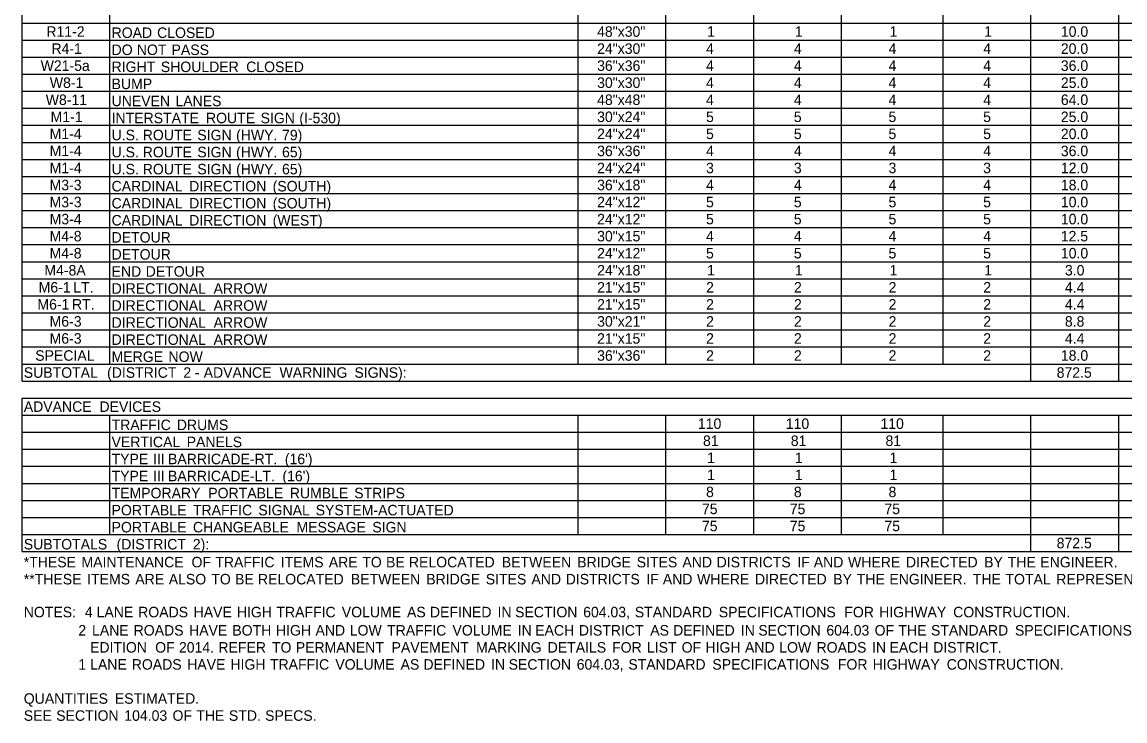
# Model space of a CAD drawing. Extents: x 542596 to 1930787, y -1948294 to 596640.
# Drawn here: x 546363 to 546993, y -1945748 to -1945349 of the extents above; entities that cross this region are included whole.
import ezdxf

# ---------------------------------------------------------------- set-up
doc = ezdxf.new("R2010")
doc.units = 0
doc.layers.add('Default', color=7, linetype='Continuous')

msp = doc.modelspace()

# ---------------------------------------------------------------- linework, layer by layer
at = {"layer": 'Default'}
for p, q in [((546362.8, -1945554.02), (546362.8, -1945125.02)), ((546362.8, -1945554.02), (546362.8, -1945125.02)), ((546413.02, -1945544.27), (546413.02, -1945193.27)), ((546413.02, -1945544.27), (546413.02, -1945193.27)), ((546680.65, -1945544.27), (546680.65, -1945193.27)), ((546680.65, -1945544.27), (546680.65, -1945193.27)), ((546730.87, -1945544.27), (546730.87, -1945193.27)), ((546730.87, -1945544.27), (546730.87, -1945193.27)), ((546781.08, -1945544.27), (546781.08, -1945193.27)), ((546831.29, -1945544.27), (546831.29, -1945193.27)), ((546831.29, -1945544.27), (546831.29, -1945193.27)), ((546889.3, -1945544.27), (546889.3, -1945193.27)), ((546939.52, -1945544.27), (546939.52, -1945193.27)), ((546939.52, -1945554.02), (546939.52, -1945193.27)), ((546989.73, -1945554.02), (546989.73, -1945193.27)), ((546989.73, -1945554.02), (546989.73, -1945193.27)), ((546362.8, -1945349.27), (547426.53, -1945349.27)), ((546781.08, -1945534.52), (546781.08, -1945349.27)), ((546362.8, -1945359.02), (547426.53, -1945359.02)), ((546362.8, -1945368.77), (547426.53, -1945368.77)), ((546362.8, -1945378.52), (547426.53, -1945378.52)), ((546362.8, -1945388.27), (547426.53, -1945388.27)), ((546362.8, -1945398.02), (547426.53, -1945398.02)), ((546362.8, -1945407.77), (547426.53, -1945407.77)), ((546362.8, -1945417.52), (547426.53, -1945417.52)), ((546362.8, -1945427.27), (547426.53, -1945427.27)), ((546362.8, -1945437.02), (547426.53, -1945437.02)), ((546362.8, -1945446.77), (547426.53, -1945446.77)), ((546362.8, -1945456.52), (547426.53, -1945456.52)), ((546362.8, -1945466.27), (547426.53, -1945466.27)), ((546362.8, -1945476.02), (547426.53, -1945476.02)), ((546362.8, -1945485.77), (547426.53, -1945485.77)), ((546362.8, -1945495.52), (547426.53, -1945495.52)), ((546362.8, -1945505.27), (547426.53, -1945505.27)), ((546362.8, -1945515.02), (547426.53, -1945515.02)), ((546362.8, -1945524.77), (547426.53, -1945524.77)), ((546362.8, -1945534.52), (547426.53, -1945534.52)), ((546362.8, -1945544.27), (546730.87, -1945544.27)), ((546362.8, -1945544.27), (547426.53, -1945544.27)), ((546730.87, -1945544.27), (546781.08, -1945544.27)), ((546781.08, -1945544.27), (546831.29, -1945544.27)), ((546362.8, -1945554.02), (547426.53, -1945554.02)), ((546362.8, -1945563.77), (547426.53, -1945563.77)), ((546362.8, -1945651.52), (546362.8, -1945563.77)), ((546362.8, -1945651.52), (546362.8, -1945563.77)), ((546413.02, -1945563.77), (547267.12, -1945563.77)), ((546362.8, -1945573.52), (547426.53, -1945573.52)), ((546413.02, -1945641.77), (546413.02, -1945573.52)), ((546413.02, -1945641.77), (546413.02, -1945573.52)), ((546680.65, -1945641.77), (546680.65, -1945573.52)), ((546680.65, -1945641.77), (546680.65, -1945573.52)), ((546730.87, -1945641.77), (546730.87, -1945573.52)), ((546730.87, -1945641.77), (546730.87, -1945573.52)), ((546781.08, -1945641.77), (546781.08, -1945573.52)), ((546781.08, -1945641.77), (546781.08, -1945573.52)), ((546831.29, -1945641.77), (546831.29, -1945573.52)), ((546831.29, -1945641.77), (546831.29, -1945573.52)), ((546889.3, -1945641.77), (546889.3, -1945573.52)), ((546939.52, -1945641.77), (546939.52, -1945573.52)), ((546939.52, -1945651.52), (546939.52, -1945573.52)), ((546989.73, -1945651.52), (546989.73, -1945573.52)), ((546989.73, -1945651.52), (546989.73, -1945573.52)), ((546362.8, -1945583.27), (547426.53, -1945583.27)), ((546362.8, -1945593.02), (547426.53, -1945593.02)), ((546362.8, -1945602.77), (547426.53, -1945602.77)), ((546362.8, -1945612.52), (547426.53, -1945612.52)), ((546362.8, -1945622.27), (547426.53, -1945622.27)), ((546362.8, -1945632.02), (547426.53, -1945632.02)), ((546680.65, -1945632.02), (547426.53, -1945632.02)), ((546362.8, -1945641.77), (546680.65, -1945641.77)), ((546362.8, -1945641.77), (547426.53, -1945641.77)), ((546362.8, -1945651.52), (547426.53, -1945651.52))]:
    msp.add_line(p, q, dxfattribs=at)

# ---------------------------------------------------------------- texts
for s, p in [('R11-2', (546376.72, -1945357.15)), ('ROAD', (546413.99, -1945357.82)), (' CLOSED', (546437.77, -1945357.82)), ('48"x30"', (546691.56, -1945357.15)), ('1', (546754.41, -1945357.15)), ('1', (546804.62, -1945357.15)), ('1', (546858.74, -1945357.15)), ('1', (546912.85, -1945357.15)), ('10.0', (546956.67, -1945357.15)), ('R4-1', (546379.6, -1945366.9)), ('DO', (546413.99, -1945367.57)), (' NOT', (546426.19, -1945367.57)), (' PASS', (546446.05, -1945367.57)), ('24"x30"', (546691.56, -1945366.9)), ('4', (546753.85, -1945366.9)), ('4', (546804.06, -1945366.9)), ('4', (546858.17, -1945366.9)), ('4', (546912.28, -1945366.9)), ('20.0', (546956.67, -1945366.9)), ('W21-5a', (546373.42, -1945376.65)), ('RIGHT', (546413.99, -1945377.32)), (' SHOULDER', (546439.9, -1945377.32)), (' CLOSED', (546488.7, -1945377.32)), ('36"x36"', (546691.56, -1945376.65)), ('4', (546753.85, -1945376.65)), ('4', (546804.06, -1945376.65)), ('4', (546858.17, -1945376.65)), ('4', (546912.28, -1945376.65)), ('36.0', (546956.67, -1945376.65)), ('W8-1', (546378.67, -1945386.4)), ('BUMP', (546413.99, -1945387.07)), ('30"x30"', (546691.56, -1945386.4)), ('4', (546753.85, -1945386.4)), ('4', (546804.06, -1945386.4)), ('4', (546858.17, -1945386.4)), ('4', (546912.28, -1945386.4)), ('25.0', (546956.67, -1945386.4)), ('W8-11', (546376.34, -1945396.15)), ('UNEVEN', (546413.99, -1945396.82)), (' LANES', (546448.25, -1945396.82)), ('48"x48"', (546691.56, -1945396.15)), ('4', (546753.85, -1945396.15)), ('4', (546804.06, -1945396.15)), ('4', (546858.17, -1945396.15)), ('4', (546912.28, -1945396.15)), ('64.0', (546956.67, -1945396.15)), ('M1-1', (546379.13, -1945405.9)), ('INTERSTATE', (546413.99, -1945406.57)), (' ROUTE', (546465.72, -1945406.57)), (' SIGN', (546496.94, -1945406.57)), (' (I-530)', (546519.08, -1945406.57)), ('30"x24"', (546691.56, -1945405.9)), ('5', (546753.81, -1945405.9)), ('5', (546804.02, -1945405.9)), ('5', (546858.13, -1945405.9)), ('5', (546912.25, -1945405.9)), ('25.0', (546956.67, -1945405.9)), ('M1-4', (546378.57, -1945415.65)), ('U.S.', (546413.99, -1945416.32)), (' ROUTE', (546429.56, -1945416.32)), (' SIGN', (546460.79, -1945416.32)), (' (HWY.', (546482.93, -1945416.32)), (' 79)', (546509.2, -1945416.32)), ('24"x24"', (546691.56, -1945415.65)), ('5', (546753.81, -1945415.65)), ('5', (546804.02, -1945415.65)), ('5', (546858.13, -1945415.65)), ('5', (546912.25, -1945415.65)), ('20.0', (546956.67, -1945415.65)), ('M1-4', (546378.57, -1945425.4)), ('U.S.', (546413.99, -1945426.07)), (' ROUTE', (546429.56, -1945426.07)), (' SIGN', (546460.79, -1945426.07)), (' (HWY.', (546482.93, -1945426.07)), (' 65)', (546509.2, -1945426.07)), ('36"x36"', (546691.56, -1945425.4)), ('4', (546753.85, -1945425.4)), ('4', (546804.06, -1945425.4)), ('4', (546858.17, -1945425.4)), ('4', (546912.28, -1945425.4)), ('36.0', (546956.67, -1945425.4)), ('M1-4', (546378.57, -1945435.15)), ('U.S.', (546413.99, -1945435.82)), (' ROUTE', (546429.56, -1945435.82)), (' SIGN', (546460.79, -1945435.82)), (' (HWY.', (546482.93, -1945435.82)), (' 65)', (546509.2, -1945435.82)), ('24"x24"', (546691.56, -1945435.15)), ('3', (546753.83, -1945435.15)), ('3', (546804.04, -1945435.15)), ('3', (546858.16, -1945435.15)), ('3', (546912.27, -1945435.15)), ('12.0', (546956.67, -1945435.15)), ('M3-3', (546378.55, -1945444.9)), ('36"x18"', (546691.56, -1945444.9)), ('4', (546753.85, -1945444.9)), ('4', (546804.06, -1945444.9)), ('4', (546858.17, -1945444.9)), ('4', (546912.28, -1945444.9)), ('18.0', (546956.67, -1945444.9)), ('CARDINAL', (546413.99, -1945445.57)), (' DIRECTION', (546456.09, -1945445.57)), (' (SOUTH)', (546503.84, -1945445.57)), ('M3-3', (546378.55, -1945454.65)), ('CARDINAL', (546413.99, -1945455.32)), (' DIRECTION', (546456.09, -1945455.32)), (' (SOUTH)', (546503.84, -1945455.32)), ('24"x12"', (546691.56, -1945454.65)), ('5', (546753.81, -1945454.65)), ('5', (546804.02, -1945454.65)), ('5', (546858.13, -1945454.65)), ('5', (546912.25, -1945454.65)), ('10.0', (546956.67, -1945454.65)), ('M3-4', (546378.57, -1945464.4)), ('CARDINAL', (546413.99, -1945465.07)), (' DIRECTION', (546456.09, -1945465.07)), (' (WEST)', (546503.84, -1945465.07)), ('24"x12"', (546691.56, -1945464.4)), ('5', (546753.81, -1945464.4)), ('5', (546804.02, -1945464.4)), ('5', (546858.13, -1945464.4)), ('5', (546912.25, -1945464.4)), ('10.0', (546956.67, -1945464.4)), ('M4-8', (546378.55, -1945474.15)), ('DETOUR', (546413.99, -1945474.82)), ('30"x15"', (546691.56, -1945474.15)), ('4', (546753.85, -1945474.15)), ('4', (546804.06, -1945474.15)), ('4', (546858.17, -1945474.15)), ('4', (546912.28, -1945474.15)), ('12.5', (546956.63, -1945474.15)), ('M4-8', (546378.55, -1945483.9)), ('DETOUR', (546413.99, -1945484.57)), ('24"x12"', (546691.56, -1945483.9)), ('5', (546753.81, -1945483.9)), ('5', (546804.02, -1945483.9)), ('5', (546858.13, -1945483.9)), ('5', (546912.25, -1945483.9)), ('10.0', (546956.67, -1945483.9)), ('M4-8A', (546375.56, -1945493.65)), ('END', (546413.99, -1945494.32)), (' DETOUR', (546431.25, -1945494.32)), ('24"x18"', (546691.56, -1945493.65)), ('1', (546754.41, -1945493.65)), ('1', (546804.62, -1945493.65)), ('1', (546858.74, -1945493.65)), ('1', (546912.85, -1945493.65)), ('3.0', (546959, -1945493.65)), ('M6-1', (546372.28, -1945503.4)), (' LT.', (546389.83, -1945503.4)), ('DIRECTIONAL', (546413.99, -1945504.07)), (' ARROW', (546470.06, -1945504.07)), ('21"x15"', (546691.56, -1945503.4)), ('2', (546753.86, -1945503.4)), ('2', (546804.08, -1945503.4)), ('2', (546858.19, -1945503.4)), ('2', (546912.3, -1945503.4)), ('4.4', (546959, -1945503.4)), ('M6-1', (546371.58, -1945513.15)), (' RT.', (546389.13, -1945513.15)), ('DIRECTIONAL', (546413.99, -1945513.82)), (' ARROW', (546470.06, -1945513.82)), ('21"x15"', (546691.56, -1945513.15)), ('2', (546753.86, -1945513.15)), ('2', (546804.08, -1945513.15)), ('2', (546858.19, -1945513.15)), ('2', (546912.3, -1945513.15)), ('4.4', (546959, -1945513.15)), ('M6-3', (546378.55, -1945522.9)), ('DIRECTIONAL', (546413.99, -1945523.57)), (' ARROW', (546470.06, -1945523.57)), ('30"x21"', (546691.56, -1945522.9)), ('2', (546753.86, -1945522.9)), ('2', (546804.08, -1945522.9)), ('2', (546858.19, -1945522.9)), ('2', (546912.3, -1945522.9)), ('8.8', (546958.98, -1945522.9)), ('M6-3', (546378.55, -1945532.65)), ('DIRECTIONAL', (546413.99, -1945533.32)), (' ARROW', (546470.06, -1945533.32)), ('21"x15"', (546691.56, -1945532.65)), ('2', (546753.86, -1945532.65)), ('2', (546804.08, -1945532.65)), ('2', (546858.19, -1945532.65)), ('2', (546912.3, -1945532.65)), ('4.4', (546959, -1945532.65)), ('SPECIAL', (546370.35, -1945542.4)), ('MERGE', (546413.99, -1945543.07)), (' NOW', (546444.29, -1945543.07)), ('36"x36"', (546691.56, -1945542.4)), ('2', (546753.86, -1945542.4)), ('2', (546804.08, -1945542.4)), ('2', (546858.19, -1945542.4)), ('2', (546912.3, -1945542.4)), ('18.0', (546956.67, -1945542.4)), ('SUBTOTAL', (546363.78, -1945552.15)), (' (DISTRICT', (546409.17, -1945552.15)), (' 2', (546452.77, -1945552.15)), (' ADVANCE', (546464.4, -1945552.15)), (' WARNING', (546507.77, -1945552.15)), (' SIGNS):', (546550.57, -1945552.15)), ('872.5', (546954.26, -1945552.15)), (' -', (546459.34, -1945552.15)), ('ADVANCE', (546363.78, -1945571.65)), (' DEVICES', (546404.82, -1945571.65)), ('TRAFFIC', (546413.99, -1945582.07)), (' DRUMS', (546449.05, -1945582.07)), ('110', (546749.18, -1945581.4)), ('110', (546799.4, -1945581.4)), ('110', (546853.51, -1945581.4)), ('VERTICAL', (546413.99, -1945591.82)), (' PANELS', (546454.69, -1945591.82)), ('81', (546752.08, -1945591.15)), ('81', (546802.29, -1945591.15)), ('81', (546856.41, -1945591.15)), ('TYPE', (546413.99, -1945601.57)), (' III', (546435.44, -1945601.57)), (' BARRICADE-RT.', (546444, -1945601.57)), (" (16')", (546510.81, -1945601.57)), ('1', (546754.41, -1945600.9)), ('1', (546804.62, -1945600.9)), ('1', (546858.74, -1945600.9)), ('TYPE', (546413.99, -1945611.32)), (' III', (546435.44, -1945611.32)), (' BARRICADE-LT.', (546444, -1945611.32)), (" (16')", (546509.42, -1945611.32)), ('1', (546754.41, -1945610.65)), ('1', (546804.62, -1945610.65)), ('1', (546858.74, -1945610.65)), ('TEMPORARY', (546413.99, -1945621.07)), (' PORTABLE', (546467.03, -1945621.07)), (' RUMBLE', (546513.64, -1945621.07)), (' STRIPS', (546550.46, -1945621.07)), ('8', (546753.83, -1945620.4)), ('8', (546804.04, -1945620.4)), ('8', (546858.15, -1945620.4)), ('PORTABLE', (546413.99, -1945630.82)), (' TRAFFIC', (546458.27, -1945630.82)), (' SIGNAL', (546495.66, -1945630.82)), (' SYSTEM-ACTUATED', (546528.44, -1945630.82)), ('75', (546751.48, -1945630.15)), ('75', (546801.69, -1945630.15)), ('75', (546855.8, -1945630.15)), ('PORTABLE', (546413.99, -1945640.57)), (' CHANGEABLE', (546458.27, -1945640.57)), (' MESSAGE', (546517.46, -1945640.57)), (' SIGN', (546560.81, -1945640.57)), ('75', (546751.48, -1945639.9)), ('75', (546801.69, -1945639.9)), ('75', (546855.8, -1945639.9)), ('SUBTOTALS', (546363.78, -1945650.32)), (' (DISTRICT', (546414.6, -1945650.32)), (' 2):', (546458.2, -1945650.32)), ('872.5', (546954.26, -1945649.65)), ('*THESE', (546363.78, -1945660.56)), (' MAINTENANCE', (546394.55, -1945660.56)), (' OF', (546457.45, -1945660.56)), (' TRAFFIC', (546471.04, -1945660.56)), (' ITEMS', (546508.43, -1945660.56)), (' ARE', (546535.94, -1945660.56)), (' TO', (546555.06, -1945660.56)), (' BE', (546568.65, -1945660.56)), (' RELOCATED', (546581.72, -1945660.56)), (' BETWEEN', (546634.84, -1945660.56)), (' BRIDGE', (546677.95, -1945660.56)), (' SITES', (546711.97, -1945660.56)), (' AND', (546738.09, -1945660.56)), (' DISTRICTS', (546757.67, -1945660.56)), (' IF', (546803.81, -1945660.56)), (' AND', (546813.2, -1945660.56)), (' WHERE', (546832.78, -1945660.56)), (' DIRECTED', (546865.87, -1945660.56)), (' BY', (546910.61, -1945660.56)), (' THE', (546924.06, -1945660.56)), (' ENGINEER.', (546942.7, -1945660.56)), ('**THESE', (546363.78, -1945670.31)), (' ITEMS', (546397.81, -1945670.31)), (' ARE', (546425.31, -1945670.31)), (' ALSO', (546444.44, -1945670.31)), (' TO', (546468.76, -1945670.31)), (' BE', (546482.35, -1945670.31)), (' RELOCATED', (546495.42, -1945670.31)), (' BETWEEN', (546548.54, -1945670.31)), (' BRIDGE', (546591.65, -1945670.31)), (' SITES', (546625.67, -1945670.31)), (' AND', (546651.79, -1945670.31)), (' DISTRICTS', (546671.37, -1945670.31)), (' IF', (546717.51, -1945670.31)), (' AND', (546726.9, -1945670.31)), (' WHERE', (546746.48, -1945670.31)), (' DIRECTED', (546779.57, -1945670.31)), (' BY', (546824.31, -1945670.31)), (' THE', (546837.76, -1945670.31)), (' ENGINEER.', (546856.4, -1945670.31)), (' THE', (546904.12, -1945670.31)), (' TOTAL', (546922.77, -1945670.31)), (' REPRESENTS', (546951.82, -1945670.31)), ('NOTES:', (546363.78, -1945689.13)), ('  4', (546394.26, -1945689.13)), (' LANE', (546403.17, -1945689.13)), (' ROADS', (546426.95, -1945689.13)), (' HAVE', (546458.65, -1945689.13)), (' HIGH', (546483.37, -1945689.13)), (' TRAFFIC', (546505.98, -1945689.13)), (' VOLUME', (546543.37, -1945689.13)), (' AS', (546580.65, -1945689.13)), (' DEFINED', (546593.73, -1945689.13)), (' IN', (546632.41, -1945689.13)), (' SECTION', (546642.43, -1945689.13)), (' 604.03,', (546681.34, -1945689.13)), (' STANDARD', (546710.88, -1945689.13)), (' SPECIFICATIONS', (546758.88, -1945689.13)), (' FOR', (546830.64, -1945689.13)), (' HIGHWAY', (546850.56, -1945689.13)), (' CONSTRUCTION.', (546892.88, -1945689.13)), ('              2', (546363.78, -1945699.56)), (' LANE', (546400.58, -1945699.56)), (' ROADS', (546424.36, -1945699.56)), (' HAVE', (546456.07, -1945699.56)), (' BOTH', (546480.78, -1945699.56)), (' HIGH', (546505.72, -1945699.56)), (' AND', (546528.33, -1945699.56)), (' LOW', (546547.92, -1945699.56)), (' TRAFFIC', (546569.24, -1945699.56)), (' VOLUME', (546606.63, -1945699.56)), (' IN', (546643.92, -1945699.56)), (' EACH', (546653.94, -1945699.56)), (' DISTRICT', (546678.89, -1945699.56)), (' AS', (546719.7, -1945699.56)), (' DEFINED', (546732.78, -1945699.56)), (' IN', (546771.46, -1945699.56)), (' SECTION', (546781.48, -1945699.56)), (' 604.03', (546820.39, -1945699.56)), (' OF', (546847.97, -1945699.56)), (' THE', (546861.55, -1945699.56)), (' STANDARD', (546880.2, -1945699.56)), (' SPECIFICATIONS', (546928.2, -1945699.56)), ('                 EDITION', (546363.78, -1945709.31)), (' OF', (546436.67, -1945709.31)), (' 2014.', (546450.25, -1945709.31)), (' REFER', (546472.82, -1945709.31)), (' TO', (546503.45, -1945709.31)), (' PERMANENT', (546517.04, -1945709.31)), (' PAVEMENT', (546571.84, -1945709.31)), (' MARKING', (546620.13, -1945709.31)), (' DETAILS', (546661.06, -1945709.31)), (' FOR', (546697.89, -1945709.31)), (' LIST', (546717.8, -1945709.31)), (' OF', (546737.66, -1945709.31)), (' HIGH', (546751.25, -1945709.31)), (' AND', (546773.86, -1945709.31)), (' LOW', (546793.44, -1945709.31)), (' ROADS', (546814.77, -1945709.31)), (' IN', (546846.47, -1945709.31)), (' EACH', (546856.5, -1945709.31)), (' DISTRICT.', (546881.44, -1945709.31)), ('              1', (546363.78, -1945719.06)), (' LANE', (546399.49, -1945719.06)), (' ROADS', (546423.27, -1945719.06)), (' HAVE', (546454.97, -1945719.06)), (' HIGH', (546479.69, -1945719.06)), (' TRAFFIC', (546502.29, -1945719.06)), (' VOLUME', (546539.69, -1945719.06)), (' AS', (546576.97, -1945719.06)), (' DEFINED', (546590.04, -1945719.06)), (' IN', (546628.72, -1945719.06)), (' SECTION', (546638.75, -1945719.06)), (' 604.03,', (546677.66, -1945719.06)), (' STANDARD', (546707.2, -1945719.06)), (' SPECIFICATIONS', (546755.2, -1945719.06)), (' FOR', (546826.96, -1945719.06)), (' HIGHWAY', (546846.87, -1945719.06)), (' CONSTRUCTION.', (546889.19, -1945719.06)), ('QUANTITIES', (546363.78, -1945738.56)), (' ESTIMATED.', (546413.65, -1945738.56)), ('SEE', (546363.78, -1945748.31)), (' SECTION', (546380.11, -1945748.31)), (' 104.03', (546419.02, -1945748.31)), (' OF', (546446.59, -1945748.31)), (' THE', (546460.18, -1945748.31)), (' STD.', (546478.83, -1945748.31)), (' SPECS.', (546499.52, -1945748.31))]:
    msp.add_text(s, height=6, dxfattribs=at).set_placement(p)

doc.saveas('drawing.dxf')
